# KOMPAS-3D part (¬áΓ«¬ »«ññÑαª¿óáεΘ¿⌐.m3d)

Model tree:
1. Эскиз:4
2. Операция выдавливания:2
     Расстояние 1 = 2; Угол 1 = 25; Расстояние 2 = 1
3. Эскиз:5
4. Вырезать элемент выдавливания:2
     Расстояние 1 = 2
5. Массив по концентрической сетке:1  (with: Вырезать элемент выдавливания:2)  (labels: Экземпляр ( 1, 1 ); Экземпляр ( 1, 2 ); Экземпляр ( 1, 3 ); Экземпляр ( 1, 4 ))
     N 2 = 10; Шаг 2 = 360
6. Эскиз:6
7. Операция выдавливания:3
     Расстояние 1 = 0.5; Расстояние 2 = 1
8. Эскиз:7
9. Операция выдавливания:4
     Расстояние 1 = 0.5; Расстояние 2 = 1
10. Эскиз:8
11. Операция выдавливания:5
     Расстояние 1 = 6; Расстояние 2 = 1
12. Эскиз:9
13. Отверстие:2
14. Эскиз:10
15. Вырезать элемент выдавливания:3
     Расстояние 1 = 2
16. Скругление:3
     Радиус = 0.1
17. Скругление:5
     Радиус = 0.1
18. Эскиз:11
19. Операция выдавливания:6
     Расстояние 1 = 0.5; Расстояние 2 = 1
20. Массив по концентрической сетке:2  (with: Операция выдавливания:6)  (labels: Экземпляр ( 1, 1 ); Экземпляр ( 1, 2 ); Экземпляр ( 1, 3 ); Экземпляр ( 1, 4 ))
     N 2 = 10; Шаг 2 = 360

Referenced files in C:\Program Files\ASCON\KOMPAS-3D V13 Home\Sys\: holelib.lfr
Referenced files in C:\Program Files\ASCON\KOMPAS-3D V12\Sys\: holelib.lfr
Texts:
  Сплав АЛ8  ГОСТ 1583-93
  Отверстие 02
  (вариант 2)
  Номер 1
  Номер 2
